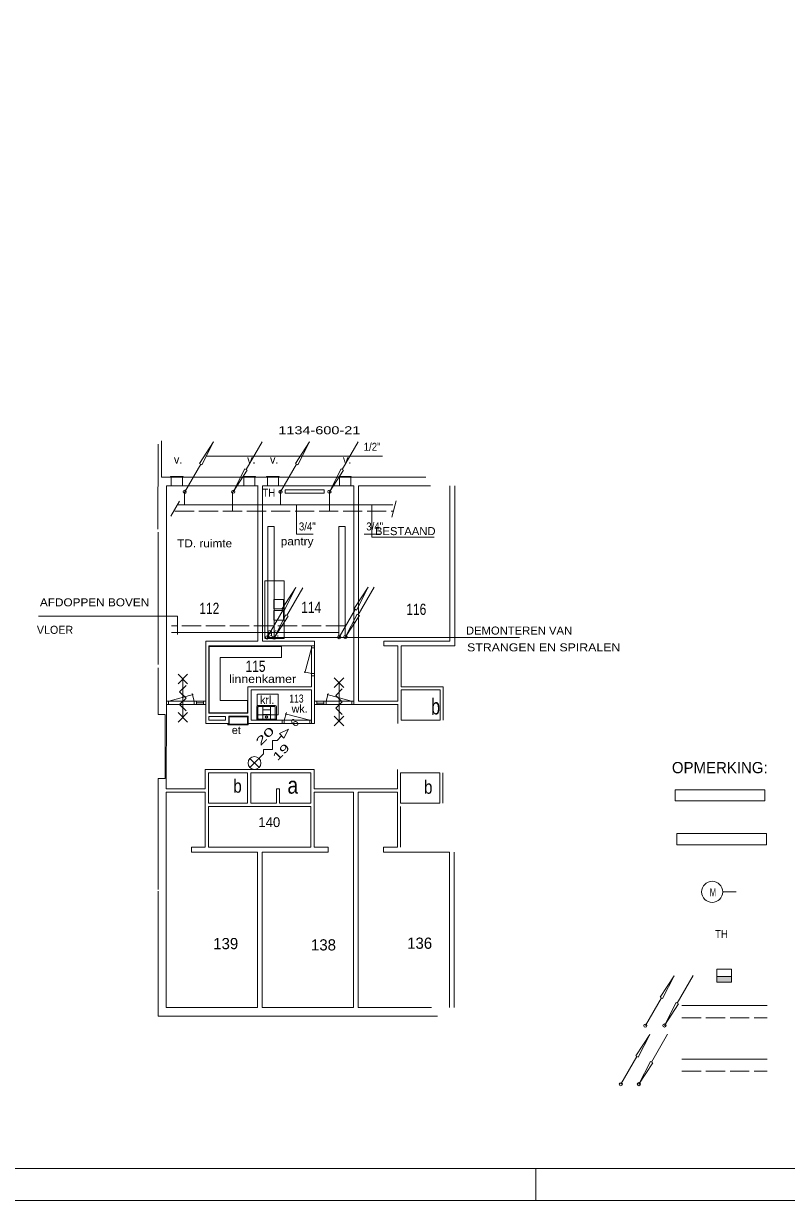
# Model space of a CAD drawing. Extents: x 295824 to 414724, y 24924 to 109024.
# Drawn here: x 356725 to 380549, y 24924 to 61673 of the extents above; entities that cross this region are included whole.
import ezdxf
from ezdxf.enums import TextEntityAlignment as Align

# ---------------------------------------------------------------- set-up
doc = ezdxf.new("R2010")
doc.units = 0
doc.header["$LTSCALE"] = 100
doc.linetypes.add('LONG_DASHED', pattern=[7.5, 6, -1.5])
for name, color, linetype, lineweight in [('1', 7, 'Continuous', 13), ('16', 7, 'Continuous', 13), ('61', 7, 'Continuous', 13)]:
    doc.layers.add(name, color=color, linetype=linetype, lineweight=lineweight)

msp = doc.modelspace()

# ---------------------------------------------------------------- hatches: boundary and pattern name
at = {"layer": '16'}
msp.add_hatch(color=256, dxfattribs=at).paths.add_polyline_path([(378371.6, 31744.1), (378834.6, 31744.1), (378834.6, 31917.1), (378371.6, 31917.1)])

# ---------------------------------------------------------------- linework, layer by layer
at = {"layer": '1'}
for p, q in [((372723.6, 24923.8), (372723.6, 25923.8)), ((304995.6, 24923.8), (414723.6, 24923.8))]:
    msp.add_line(p, q, dxfattribs=at)
msp.add_lwpolyline([(304995.6, 25923.8), (413723.6, 25923.8), (413723.6, 108023.8), (304995.6, 108023.8)], dxfattribs=at)
at = {"layer": '16'}
for p, q in [((364173.6, 48612.3), (363673.6, 47746.3)), ((367177.8, 48612.3), (366677.8, 47746.3)), ((362418.7, 48166.5), (367932, 48166.5)), ((361758.3, 47050.2), (362258.3, 47916.2)), ((364750.7, 47050.2), (365250.7, 47916.2)), ((361752.6, 47050.2), (361752.6, 46648.7)), ((364750.7, 47050.2), (364750.7, 46648.7)), ((361592.8, 46760.8), (361319.5, 46287.4)), ((368361.7, 46770.5), (368224.2, 46257.1)), ((361519.3, 46648.7), (368253.9, 46648.7)), ((367356.5, 45732.8), (367874.9, 45732.8)), ((365450.2, 44053.6), (364950.2, 43187.6)), ((367677.3, 44077.5), (367177.3, 43211.5)), ((364331.7, 42503.5), (364831.7, 43369.5)), ((366582.6, 42515.4), (367082.6, 43381.4)), ((366553.4, 42663.3), (361348.9, 42663.3)), ((364329.2, 42496.8), (372213.3, 42496.8)), ((378557.6, 34558.9), (378982.4, 34558.9)), ((378834.6, 31917.1), (378834.6, 32144.9)), ((377638, 31946.1), (377138, 31080.1)), ((376143.7, 30383.9), (376643.7, 31249.9)), ((377285.8, 31007.7), (379948.4, 31007.7)), ((376838.5, 30112.8), (376338.5, 29246.8)), ((375377.5, 28550.6), (375877.5, 29416.6)), ((377285.8, 29339.9), (379948.4, 29339.9))]:
    msp.add_line(p, q, dxfattribs=at)
at = {"layer": '16', "linetype": 'LONG_DASHED'}
for p, q in [((363246.4, 47053.3), (363246.4, 46448.7)), ((366277.8, 47053.3), (366277.8, 46448.7)), ((361452.7, 46448.7), (368253.9, 46448.7)), ((366769.6, 42863.3), (361348.9, 42863.3)), ((377285.8, 30630.5), (379948.4, 30630.5)), ((377285.8, 28962.7), (379948.4, 28962.7))]:
    msp.add_line(p, q, dxfattribs=at)
at = {"layer": '16'}
for points in [[(362658.3, 48609.2), (362294.3, 47895.2), (362222.3, 47937.2)], [(365650.7, 48609.2), (365286.7, 47895.2), (365214.7, 47937.2)], [(363273.6, 47053.3), (363637.6, 47767.3), (363709.6, 47725.3)], [(366277.8, 47053.3), (366641.8, 47767.3), (366713.8, 47725.3)], [(364899.6, 47007.8), (366116.3, 47007.8), (366116.3, 47115), (364899.6, 47115)], [(365231.7, 44062.5), (364867.7, 43348.5), (364795.7, 43390.5)], [(367482.6, 44074.4), (367118.6, 43360.4), (367046.6, 43402.4)], [(364550.2, 42494.6), (364914.2, 43208.6), (364986.2, 43166.6)], [(366777.3, 42518.5), (367141.3, 43232.5), (367213.3, 43190.5)], [(377073.6, 37396.8), (379877.5, 37396.8), (379877.5, 37750.4), (377073.6, 37750.4)], [(377120.7, 36029.3), (379924.7, 36029.3), (379924.7, 36383), (377120.7, 36383)], [(377043.7, 31942.9), (376679.7, 31228.9), (376607.7, 31270.9)], [(378371.6, 31744.1), (378834.6, 31744.1), (378834.6, 31917.1), (378371.6, 31917.1)], [(376738, 30387.1), (377102, 31101.1), (377174, 31059.1)], [(376277.5, 30109.6), (375913.5, 29395.6), (375841.5, 29437.6)], [(375938.5, 28553.8), (376302.5, 29267.8), (376374.5, 29225.8)]]:
    msp.add_lwpolyline(points, close=True, dxfattribs=at)
for points in [[(365251.5, 46648.7), (365251.5, 45732.8), (365769.9, 45732.8)], [(367598.8, 46649.8), (367598.8, 45633.2), (369547.6, 45633.2)], [(364351.9, 42537.4), (364351.9, 45969.3), (364554.4, 45969.3), (364554.4, 42549.3)], [(366567.1, 42537.4), (366567.1, 45969.3), (366769.6, 45969.3), (366769.6, 42549.3)], [(361527.5, 42591.8), (361527.5, 43163.8), (357192.5, 43163.8)], [(378371.6, 31917.1), (378371.6, 32144.9), (378834.6, 32144.9)]]:
    msp.add_lwpolyline(points, dxfattribs=at)
for centre, radius in [((361758.3, 47049.8), 50), ((363273.6, 47053.6), 50), ((364750.7, 47049.8), 50), ((366277.8, 47053.6), 50), ((364331.7, 42503.2), 50), ((364550.2, 42494.9), 50), ((366582.6, 42515.1), 50), ((366777.3, 42518.8), 50), ((378227.7, 34558.9), 329.9), ((376143.6, 30383.6), 50), ((376738, 30387.4), 50), ((375377.5, 28550.3), 50), ((375938.5, 28554.1), 50)]:
    msp.add_circle(centre, radius, dxfattribs=at)
at = {"layer": '61'}
for p, q in [((360918.7, 45887.9), (360931.7, 48537.9)), ((361031.7, 48637.9), (361031.7, 47511.4)), ((361031.7, 47511.4), (369284.8, 47511.4)), ((361708, 47527.5), (361314.8, 47527.5)), ((361314.8, 47527.5), (361314.8, 47510)), ((361708, 47510), (361314.8, 47510)), ((361338.9, 47510), (361338.9, 47238.9)), ((361688.9, 47507.7), (361688.9, 47238.9)), ((361708, 47527.5), (361708, 47510)), ((363970.3, 47527.5), (363577.1, 47527.5)), ((363577.1, 47527.5), (363577.1, 47510)), ((363970.3, 47510), (363577.1, 47510)), ((363601.1, 47510), (363601.1, 47238.9)), ((363951.1, 47507.8), (363951.1, 47238.9)), ((363970.3, 47527.5), (363970.3, 47510)), ((364708.8, 47527.5), (364315.6, 47527.5)), ((364315.6, 47527.5), (364315.6, 47510)), ((364708.8, 47510), (364315.6, 47510)), ((364339.6, 47510), (364339.6, 47238.9)), ((364689.6, 47507.7), (364689.6, 47238.9)), ((364708.8, 47527.5), (364708.8, 47510)), ((366959.9, 47527.5), (366566.7, 47527.5)), ((366566.7, 47527.5), (366566.7, 47510)), ((366959.9, 47510), (366566.7, 47510)), ((366590.7, 47510), (366590.7, 47238.9)), ((366940.7, 47507.8), (366940.7, 47238.9)), ((366959.9, 47527.5), (366959.9, 47510)), ((361187.9, 47241.4), (361787.9, 47241.4)), ((361188.7, 40516.4), (361188.7, 47241.4)), ((363449.6, 47241.4), (364049, 47241.4)), ((363961.5, 47238.9), (363568.3, 47238.9)), ((367038.7, 47238.9), (364306.8, 47238.9)), ((367038.7, 47241.4), (364888.7, 47241.4)), ((366439.2, 47241.4), (367038.7, 47241.4)), ((366951.2, 47238.9), (366558, 47238.9)), ((367038.7, 40405.5), (367038.7, 47238.9)), ((367188.7, 47241.4), (369431.5, 47241.4)), ((370188.7, 47241.4), (370188.7, 42241.3)), ((360931.7, 45787.9), (360931.7, 41658.1)), ((364188.7, 42391.4), (365813.7, 42391.4)), ((364266.1, 42467.5), (364863.2, 42467.5)), ((365813.7, 42391.4), (365813.7, 42241.4)), ((362513.7, 42241.4), (365813.7, 42241.4)), ((362513.7, 40136.4), (362513.7, 42241.4)), ((365713.6, 42170.8), (365506.7, 41398.6)), ((365813.5, 42174.4), (365713.3, 42174.4)), ((365813.3, 42241.4), (365713.7, 42241.4)), ((365713.7, 42241.4), (365713.7, 40966.4)), ((365813.3, 42241.4), (365813.3, 41307.4)), ((368513.7, 40963.7), (368513.7, 42241.3)), ((370188.7, 42241.3), (368513.7, 42241.3)), ((361848.8, 41358), (361548.8, 41058)), ((361548.8, 41358), (361848.8, 41058)), ((361698.8, 40008), (361698.8, 41208)), ((365713.6, 41373.3), (365486.3, 41434.2)), ((365713.3, 41307.4), (365713.3, 41305.7)), ((365813.7, 41307.4), (365713.3, 41307.4)), ((365813.2, 41374.4), (365713.9, 41374.4)), ((365813.7, 41307.4), (365813.7, 40516.4)), ((366729.4, 41244.4), (366429.4, 40944.4)), ((366429.4, 41244.4), (366729.4, 40944.4)), ((365713.7, 40966.4), (363733.7, 40966.4)), ((363733.7, 40966.4), (363733.7, 40136.4)), ((366579.4, 39894.4), (366579.4, 41094.4)), ((368513.7, 40963.7), (369833.7, 40963.7)), ((369833.7, 39916.4), (369833.7, 40963.7)), ((361255.5, 40406.1), (361255.5, 40516.1)), ((361258.1, 40516.3), (362025.4, 40721.9)), ((362052.7, 40514.1), (361987.6, 40756.9)), ((362055.5, 40406.1), (362055.5, 40516.1)), ((362122.5, 40406.1), (362122.5, 40516.1)), ((362123.3, 40456.9), (362348, 40456.9)), ((362348, 40406.1), (362348, 40516.1)), ((364023.8, 40085.7), (364023.8, 40735.7)), ((364028.2, 40735.5), (364678.2, 40735.5)), ((364676.5, 40085.7), (364676.5, 40735.7)), ((365879.5, 40405.3), (365879.5, 40515.3)), ((366104.1, 40456.1), (365879.5, 40456.1)), ((366105, 40405.3), (366105, 40515.3)), ((366172, 40405.3), (366172, 40515.3)), ((366174.8, 40513.3), (366239.8, 40756.1)), ((366969.4, 40515.5), (366202.1, 40721.1)), ((366972, 40405.3), (366972, 40515.3)), ((361848.8, 40158), (361548.8, 39858)), ((361548.8, 40158), (361848.8, 39858)), ((362413.7, 40406.4), (362413.7, 39816.4)), ((363733.7, 40136.4), (362513.7, 40136.4)), ((364010.2, 40345.4), (364010.2, 39930.4)), ((364028.2, 40086.8), (364678.2, 40086.8)), ((364585.2, 40380.4), (364045.2, 40380.4)), ((364045.2, 39970.4), (364045.2, 40330.4)), ((364060.2, 40345.4), (364570.2, 40345.4)), ((364195.2, 39955.4), (364195.2, 40380.4)), ((364435.2, 40238.8), (364195.2, 40238.8)), ((364435.2, 40097.1), (364195.2, 40097.1)), ((364435.2, 39955.4), (364435.2, 40380.4)), ((364585.2, 40330.4), (364585.2, 39970.4)), ((364620.2, 39930.4), (364620.2, 40345.4)), ((364868.2, 39913.8), (364933.2, 40156.6)), ((365662.8, 39916), (364895.5, 40121.6)), ((365813.7, 39816.4), (365813.7, 40416.4)), ((367038.7, 40405.5), (368413.7, 40405.5)), ((368413.7, 40416.4), (368413.7, 39816.4)), ((362413.7, 39816.4), (363138, 39816.4)), ((362513.7, 39916.4), (362513.7, 40036.4)), ((363033.7, 40036.4), (362513.7, 40036.4)), ((362513.7, 39916.4), (363033.7, 39916.4)), ((363033.7, 40036.4), (363033.7, 39916.4)), ((363109.5, 39792.7), (363740.8, 39792.7)), ((363109.5, 39775.2), (363109.5, 39792.7)), ((363109.5, 39775.2), (363740.8, 39775.2)), ((363138, 40043), (363138, 39816.4)), ((363738, 40043), (363138, 40043)), ((363148.8, 39792.7), (363148.8, 40027.7)), ((363148.8, 40027.7), (363714.2, 40027.7)), ((363714.2, 39792.6), (363714.2, 40027.7)), ((363738, 40043), (363738, 39816.4)), ((363738, 39816.4), (365813.7, 39816.4)), ((363740.8, 39775.2), (363740.8, 39792.7)), ((364610.2, 39955.4), (364020.2, 39955.4)), ((364020.2, 39920.4), (364610.2, 39920.4)), ((364798.4, 39816.5), (364798.4, 39915.8)), ((364865.4, 39819.9), (364865.4, 39915.8)), ((365665.4, 39816.5), (365665.4, 39915.8)), ((366729.4, 40044.4), (366429.4, 39744.4)), ((366429.4, 40044.4), (366729.4, 39744.4)), ((363795.3, 38723), (364078.1, 38440.2)), ((369820.9, 38277.1), (369820.9, 37327.1)), ((368500.9, 37227.1), (368500.9, 35952.1)), ((370175.9, 30952.1), (370175.9, 35802.1)), ((360931.7, 30682.1), (360931.7, 34578.2)), ((367175.9, 30952.1), (369468.2, 30952.1)), ((369651.6, 30682.1), (360931.7, 30682.1))]:
    msp.add_line(p, q, dxfattribs=at)
for points in [[(361188.7, 47241.4), (364038.7, 47241.4), (364038.7, 42391.4), (362413.7, 42391.4), (362413.7, 40516.9)], [(364188.7, 42391.4), (364188.7, 47241.4), (364788.7, 47241.4)], [(370038.7, 47241.4), (370038.7, 42391.4), (367978.7, 42391.4), (367978.7, 42241.4), (368413.7, 42241.4), (368413.7, 40516.4), (367188.7, 40516.4), (367188.7, 47241.4)], [(364863.2, 42467.5), (364863.2, 44267.5), (364263.2, 44267.5), (364263.2, 42474.2)], [(360931.7, 41558.1), (360931.7, 40096.8), (361151.7, 40096.8), (361151.7, 38096.8), (360931.7, 38096.8), (360931.7, 34630.7)], [(361798.8, 40208), (361598.8, 40408), (361798.8, 40608), (361598.8, 40808), (361798.8, 41008)], [(363833.7, 40866.4), (365713.7, 40866.4), (365713.7, 39816.4)], [(365713.7, 39916.4), (363833.7, 39916.4), (363833.7, 40866.4)], [(366679.4, 40094.4), (366479.4, 40294.4), (366679.4, 40494.4), (366479.4, 40694.4), (366679.4, 40894.4)], [(368400.9, 38377.1), (368400.9, 37777.1), (365800.9, 37777.1), (365800.9, 38377.1), (362400.9, 38377.1), (362400.9, 37777.1), (361175.9, 37777.1), (361188.7, 40416.4)], [(363795.3, 38440.2), (364219.6, 38864.4), (364219.6, 39005.8), (364502.4, 39005.8), (364502.4, 39288.7), (364643.8, 39288.7), (364785.2, 39430.1)], [(370025.9, 30952.1), (370025.9, 35802.1), (367965.9, 35802.1), (367965.9, 35952.1), (368400.9, 35952.1), (368400.9, 37677.1), (367175.9, 37677.1), (367175.9, 30952.1)]]:
    msp.add_lwpolyline(points, dxfattribs=at)
for points in [[(364838.2, 43392.5), (364838.2, 43692.5), (364538.2, 43692.5), (364538.2, 43392.5)], [(364838.2, 43042.2), (364838.2, 43342.2), (364538.2, 43342.2), (364538.2, 43042.2)], [(364776.8, 42220.8), (364776.8, 41876.1), (362865.2, 41876.1), (362865.2, 40530.5), (363723.5, 40530.5), (363723.5, 40149.7), (362523.5, 40149.7), (362523.5, 42220.8)], [(368513.7, 40866.4), (369733.7, 40866.4), (369733.7, 39916.4), (368513.7, 39916.4)], [(361189.6, 40406.5), (361189.6, 40516.9), (362413.9, 40516.9), (362413.9, 40406.5)], [(367037.9, 40405.7), (367037.9, 40516.1), (365813.5, 40516.1), (365813.5, 40405.7)], [(364856, 39359.4), (364714.5, 39500.8), (364997.4, 39642.2)], [(362500.9, 37327.1), (363720.9, 37327.1), (363720.9, 38277.1), (362500.9, 38277.1)], [(363820.9, 37327.1), (364620.9, 37327.1), (364620.9, 37777.1), (364720.9, 37777.1), (364720.9, 37327.1), (365700.9, 37327.1), (365700.9, 38277.1), (363820.9, 38277.1)], [(368500.9, 37327.1), (369720.9, 37327.1), (369720.9, 38277.1), (368500.9, 38277.1)], [(361175.9, 30952.1), (364025.9, 30952.1), (364025.9, 35802.1), (361965.9, 35802.1), (361965.9, 35952.1), (362400.9, 35952.1), (362400.9, 37677.1), (361175.9, 37677.1)], [(367025.9, 30952.1), (364175.9, 30952.1), (364175.9, 35802.1), (366235.9, 35802.1), (366235.9, 35952.1), (365800.9, 35952.1), (365800.9, 37677.1), (367025.9, 37677.1)], [(362500.9, 35952.1), (365700.9, 35952.1), (365700.9, 37227.1), (362500.9, 37227.1)]]:
    msp.add_lwpolyline(points, close=True, dxfattribs=at)
for centre, radius in [((364315.2, 40020.4), 40), ((364315.2, 40020.4), 30), ((363936.7, 38581.6), 200)]:
    msp.add_circle(centre, radius, dxfattribs=at)
for centre, radius, start, end in [((364045.2, 40345.4), 35, 90, 180), ((364060.2, 40330.4), 15, 90, 180), ((364570.2, 40330.4), 15, 0, 90), ((364585.2, 40345.4), 35, 0, 90), ((364020.2, 39945.4), 10, 90, 180), ((364020.2, 39930.4), 10, 180, 270), ((364060.2, 39970.4), 15, 180, 270), ((364570.2, 39970.4), 15, 270, 0), ((364610.2, 39945.4), 10, 0, 90), ((364610.2, 39930.4), 10, 270, 0)]:
    msp.add_arc(centre, radius, start, end, dxfattribs=at)

# ---------------------------------------------------------------- texts
at = {"layer": '16'}
for s, width, p in [('1134-600-21', 1.35, (364681.6, 48847.9)), ('1/2"', 0.9, (367346.6, 48331.3)), ('TH', 0.9, (364183.8, 46898.7)), ('3/4"', 0.9, (365323, 45844.9)), ('3/4"', 0.9, (367428, 45844.9)), ('BESTAAND', 1.05, (367698.3, 45698.8)), ('AFDOPPEN BOVEN', 1.1, (357236.6, 43475.2)), ('DEMONTEREN VAN', 1.05, (370540, 42593.6)), ('STRANGEN EN SPIRALEN', 1.15, (370575.7, 42069.3)), ('M', 0.65, (378154.3, 34416.3)), ('TH', 0.9, (378319.5, 33118.6))]:
    msp.add_text(s, height=250, dxfattribs=dict(at, width=width)).set_placement(p)
for s, height, p in [('VLOER', 250, (357141.3, 42617.2)), ('OPMERKING:', 350, (376971.2, 38264.2))]:
    msp.add_text(s, height=height, dxfattribs=at).set_placement(p)
at = {"layer": '61'}
for s, height, p in [('v.', 250, (361421.8, 47933.8)), ('v.', 250, (363708, 47933.8)), ('v.', 250, (364422.6, 47933.8)), ('v.', 250, (366697.6, 47933.8)), ('ar.', 250, (364324.1, 42531.2)), ('krl.', 250, (364111.2, 40428.5)), ('wk.', 250, (365097.5, 40152.8)), ('et', 250, (363229.6, 39487.7)), ('139', 350, (362648.1, 32769.3)), ('138', 350, (365700.7, 32729.2)), ('136', 350, (368704, 32781.5))]:
    msp.add_text(s, height=height, dxfattribs=at).set_placement(p)
for s, height, width, p in [('TD. ruimte', 250, 1.1, (361521.4, 45317.3)), ('pantry', 250, 1.1, (364757, 45381.3)), ('112', 350, 0.8, (362213.6, 43237.8)), ('114', 350, 0.8, (365394.9, 43267.4)), ('116', 350, 0.8, (368677.5, 43208.3)), ('115', 350, 0.8, (363656.4, 41429.4)), ('linnenkamer', 250, 1.15, (363141.5, 41083.7)), ('113', 250, 0.8, (365024.3, 40471.1)), ('b', 500, 0.75, (369452.3, 40097.6))]:
    msp.add_text(s, height=height, dxfattribs=dict(at, width=width)).set_placement(p)
msp.add_text('6', height=250, rotation=45, dxfattribs=at).set_placement((365211.9, 39688.1))
for s, width, p in [('20', 1.75, (364121.9, 39104.1)), ('19', 1.55, (364650.4, 38631.8))]:
    msp.add_text(s, height=250, rotation=45, dxfattribs=dict(at, width=width)).set_placement(p)
at = {"layer": '61', "width": 0.85}
for s, height, p in [('b', 420, (363407, 37655.5)), ('a', 525, (365132.8, 37625.8)), ('b', 420, (369361.8, 37622.6))]:
    msp.add_text(s, height=height, dxfattribs=at).set_placement(p, align=Align.CENTER)
at = {"layer": '61'}
msp.add_text('140', height=306.2, dxfattribs=at).set_placement((364399, 36582.3), align=Align.CENTER)

doc.saveas('drawing.dxf')
